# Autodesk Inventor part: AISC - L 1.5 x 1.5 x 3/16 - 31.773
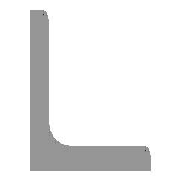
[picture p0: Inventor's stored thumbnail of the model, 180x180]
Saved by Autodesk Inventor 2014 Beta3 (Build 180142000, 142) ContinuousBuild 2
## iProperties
_CCFamilyMember: 5
_CCFamilyDisplayName: ANSI L (Equal angles) - Angle Steel
_FrameMemberDoc: Frame Member File
_Version: 15.0.0
_GetPNFromCC: 1
Created: 2010-11
Part Number: AISC - L 1.5 x 1.5 x 3/16 - 31.773
Material: Steel, Mild
Description: Angle Steel
Document SubType Name: Modeling
Standard: ANSI
Designer: Beta-8540w
Standards Organization: ANSI
Language: en-US
Size Designation: L 1.5 x 1.5 x 3/16
Categories: <MemberInstance><Categories><Category DisplayName="Structural Shapes" InternalName="089c4875-fa83-4c05-b084-43b9cc11f5ed" Mnemonic="GRDR"><CategoryParameter Dis
Stock Number: L 1.5 x 1.5 x 3/16
Density: 7.86 g/cm^3
Appearance: Steel
IsCustomPart: 1
G_L: 31.773 in
G_W: 1.500 in
G_H: 1.500 in
+3B2E30B5-4963-484D-8D95-D946A704ABD9+CUTDETAIL1: Cut
Author: Beta-8540w
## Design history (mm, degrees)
node "Start plane"
node "End plane"
sketch "Sketch"
  geometry: L1 (38.1, 0)-(0, 0); L2 (0, 0)-(0, 38.1); L3 (0, 38.1)-(2.476, 38.1); L4 (4.762, 35.814)-(4.762, 9.589); L5 (9.588, 4.763)-(35.814, 4.763); L6 (38.1, 2.477)-(38.1, 0); L7 (0, -11.041)-(0, 31.538); L8 (-11.041, 0)-(31.538, 0); L9 (0, 48.496)-(0, -20.964) reference; L10 (-20.964, 0)-(48.496, 0) reference; A1 r 4.826 centre (9.588, 9.589) between (4.762, 9.589) and (9.588, 4.763); A2 r 2.286 centre (2.476, 35.814) between (4.762, 35.814) and (2.476, 38.1); A3 r 2.286 centre (35.814, 2.477) between (38.1, 2.477) and (35.814, 4.763); 3 further points
  constraints: 16 end point, 6 point on circle, 6 point on line, 6 tangent, 4 parallel, 3 centre point, 2 collinear, 1 equal radius, 1 horizontal, 1 perpendicular
  dimensions: "d0" = 38.1 distance between parallel lines of L6 L2 (= G_H); "d1" = 38.1 distance between parallel lines of L3 L1 (= G_H); "d2" = 4.7625 distance between parallel lines of L2 L4 (= G_T); "d3" = 4.7625 distance between parallel lines of L1 L5 (= G_T); "d10" = 0 distance between parallel lines of L7 L2 (computed from ex); "d11" = 0 distance between parallel lines of L8 L1 (computed from d10); "d14" = 4.826 radius of A1 (= G_IR); "d15" = 2.286 radius of A2 (= G_ER)
extrude "Body" new body sketch "Sketch" stored distance "d4" = 807.0404 (= G_L); taper "d5" = 0 deg
node "Driven Length"
  sketch "Sketch3"
    geometry: L1 (0, 0)-(10, 0) reference
    constraints: 2 end point, 1 horizontal
  workplane "Work Plane3"
  sketch "Sketch4"
    geometry: L1 (-2, 0)-(12, 0) reference; L2 (-2, 807.04)-(12, 807.04) reference
    dimensions: "d17" = 807.0404 distance between parallel lines of L1 L2 (derived)
workplane "Work Plane4"
split "Split1"
body "Solid1"
other parameters: "G_H" = 38.1 [user parameter; used in 2 equation terms], "G_T" = 4.7625 [user parameter; used in 2 equation terms], "G_ER" = 2.286 [user parameter; used in 1 equation term], "G_IR" = 4.826 [user parameter; used in 1 equation term], "G_L" = 807.0404 (= d17) [user parameter; used in 1 equation term], "ex" = 0 [user parameter; used in 1 equation term], "G_OFFSET_START" = 0 [user parameter; used in 1 equation term], "G_OFFSET_END" = -29.72503 [user parameter; used in 1 equation term], "d12" = 0 (computed from G_OFFSET_START), "d13" = 807.0404 (= G_OFFSET_END + B_L), "B_L" = 836.76542 [user parameter; used in 1 equation term], "d16" = 90 deg, "MAS" = 0.26787 [user parameter]
